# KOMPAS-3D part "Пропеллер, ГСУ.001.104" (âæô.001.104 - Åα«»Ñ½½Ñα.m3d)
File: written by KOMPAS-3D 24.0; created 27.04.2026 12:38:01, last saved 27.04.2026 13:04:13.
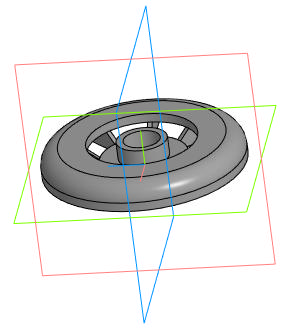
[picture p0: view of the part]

Document properties: Автор: User7; Полное имя файла: C:\Users\User7\Desktop\олимп\ГСУ.001.104 - Пропеллер.m3d

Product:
- Part/product: Пропеллер  | designation ГСУ.001.104
    Масса: 0.031447

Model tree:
1. Эскиз:1
2. Элемент вращения:1
     Угол 1 = 360
3. Эскиз:2  (with: Грань.Элемент вращения:1, Ребро.Элемент вращения:1, Вершина.Элемент вращения:1)
4. Элемент выдавливания:1
     Расстояние 1 = 1
5. Массив по концентрической сетке:1  (with: Элемент выдавливания:1, Эскиз:2, Грань.Элемент вращения:1)  (8 pattern instances)
     Шаг 2 = 360

Expressions: 11/2
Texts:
  ГСУ.001.104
